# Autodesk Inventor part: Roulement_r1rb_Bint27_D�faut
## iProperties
Created: 2011-01
Part Number: Roulement_r1rb_Bint27_D�faut
Document SubType Name: Modeling
Designer: eric
Density: 1 g/cm^3
Mass: 0.766536 g
Surface Area: 9.42224 cm^2
Volume: 0.766536 cm^3
Author: eric
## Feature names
1. Base1
